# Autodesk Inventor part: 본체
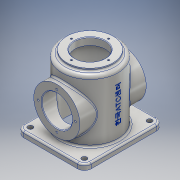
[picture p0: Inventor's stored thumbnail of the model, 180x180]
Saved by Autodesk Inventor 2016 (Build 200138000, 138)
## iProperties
Created: 2021-02
Part Number: 본체
Material: 알루미늄 6061
Document SubType Name: Modeling
Designer: user
Density: 2.7 g/cm^3
Appearance: 알루미늄 - 평지
Mass: 1236.22 g
Surface Area: 1064.5 cm^2
Volume: 457.859 cm^3
Author: user
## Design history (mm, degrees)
sketch "스케치5"
  geometry: L1 (-60, -70)-(60, -70); L2 (60, -70)-(60, 70); L3 (60, 70)-(-60, 70); L4 (-60, 70)-(-60, -70); L5 (-60, -70)-(60, 70); L6 (60, -70)-(-60, 70); 1 further point
  constraints: 12 end point, 2 midpoint, 2 parallel, 1 horizontal, 1 perpendicular
  dimensions: "d28" = 120 distance of L3.end L2.end; "d29" = 140 distance of L2.end L1.end
extrude "돌출4" new body sketch "스케치5" distance "d30" = 10; taper "d31" = 0 deg
sketch "스케치6"
  geometry: C1 r 50 at (0, 0); 1 further point
  constraints: 1 centre point, 1 coincident
  dimensions: "d32" = 100 diameter of C1
extrude "돌출5" join sketch "스케치6" distance "d33" = 110; taper "d34" = 0 deg
sketch "스케치7"
  geometry: C1 r 41 at (0, 0); 1 further point
  constraints: 1 centre point, 1 coincident
  dimensions: "d35" = 82 diameter of C1
extrude "돌출6" join sketch "스케치7" distance "d36" = 5; taper "d37" = 0 deg
hole "구멍3" diameter "d40" = 54; stored, may be unused: countersink angle "d44" = 90 deg, drill point angle "d46" = 0 deg; dims "d38" = 10, "d39" = 10, "d41" = 6, "d42" = 54, "d43" = 13, "d45" = 13
hole "구멍4" diameter "d49" = 84; stored, may be unused: countersink angle "d53" = 90 deg, drill point angle "d55" = 0 deg; dims "d47" = 60, "d48" = 70.058, "d50" = 6, "d51" = 54, "d52" = 13, "d54" = 112
node "작업 평면1"
sketch "스케치10"
  geometry: L1 (60, 0)-(-60, 0) reference; C1 r 41 at (0, 60); 1 further point
  constraints: 1 centre point
  dimensions: "d57" = 82 diameter of C1; "d58" = 60 distance of point (0, 0) C1.centre; "d59" = 60 distance from line of L1 C1.centre
extrude "돌출7" join sketch "스케치10" stored distance "d60" = 15; taper "d61" = 0 deg
hole "구멍5" diameter "d64" = 54; stored, may be unused: countersink angle "d68" = 90 deg, drill point angle "d70" = 0 deg; dims "d62" = 10, "d63" = 10, "d65" = 6, "d66" = 54, "d67" = 13, "d69" = 59
sketch "스케치11" dims "d71" = 66
  geometry: C1 r 41 at (0, 0) reference; 3 further points
  constraints: 2 vertical alignment, 1 coincident, 2 other
hole "구멍6" sketch "스케치11" at (0, 33) diameter "d72" = 3.242; stored, may be unused: countersink angle "d76" = 90 deg, drill point angle "d78" = 118 deg; dims "d73" = 8, "d74" = 54, "d75" = 13, "d77" = 10
sketch "스케치12" dims "d82" = 66
  geometry: C1 r 41 at (0, 0) reference; 3 further points
  constraints: 2 vertical alignment, 1 coincident, 2 other
hole "구멍7" sketch "스케치12" at (0, 33) diameter "d83" = 3.242; stored, may be unused: countersink angle "d87" = 90 deg, drill point angle "d89" = 118 deg; dims "d84" = 8, "d85" = 54, "d86" = 13, "d88" = 10
fillet "모깎기1" dims "d93" = 12
chamfer "모따기1" distance "d94" = 1; stored, may be unused: second distance "d95" = 2, angle "d96" = 45 deg
hole "구멍8" diameter "d99" = 9; stored, may be unused: countersink angle "d103" = 90 deg, drill point angle "d105" = 0 deg; dims "d97" = 10, "d98" = 10, "d100" = 8, "d101" = 54, "d102" = 13, "d104" = 10
fillet "모깎기2" dims "d112" = 3
fillet "모깎기3" dims "d113" = 6
fillet "모깎기4" dims "d114" = 3
fillet "모깎기5" dims "d115" = 3
node "작업 평면2"
sketch "스케치13"
  geometry: 1 further point
sketch "스케치14"
  geometry: L1 (-58, 0)-(58, 0) reference; 2 further points
  constraints: 1 other
  dimensions: "d117" = 66 distance from line of L1 point (0, 66); "d118" = 0 horizontal distance of point (0, 0) point (0, 66)
feature "엠보싱1" sketch "스케치14" dims "d28" = 120, "d29" = 140, "d119" = 0.5, "d120" = 0
node "솔리드2"
pattern_circular "원형 패턴1" dims angle "d80" = 360 deg
mirror "대칭1"
pattern_circular "원형 패턴2" dims angle "d91" = 360 deg
pattern_linear "직사각형 패턴1" dims "d108" = 96, "d111" = 116
other parameters: "d56" = -59
